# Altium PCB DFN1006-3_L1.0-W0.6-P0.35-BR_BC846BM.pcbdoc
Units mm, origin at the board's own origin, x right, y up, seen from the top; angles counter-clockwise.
Board outline 13.99 x 13.6 mm, 2 copper layers (Top Layer, Bottom Layer), stack 0 mm thick; 1 components, 0 nets, 3 pads, 0 vias.
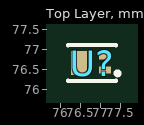
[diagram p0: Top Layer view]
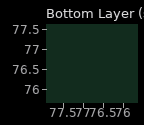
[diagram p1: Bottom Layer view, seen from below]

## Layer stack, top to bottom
Top Layer: signal copper (thickness not stored)
Bottom Layer: signal copper (thickness not stored)

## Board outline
83.835,69.85 69.85,69.85 69.85,83.45 83.835,83.45

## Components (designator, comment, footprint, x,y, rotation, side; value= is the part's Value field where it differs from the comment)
U? "" DFN1006-3_L1.0-W0.6-P0.35-BR_BC846BM 76.8,76.65 r0 top

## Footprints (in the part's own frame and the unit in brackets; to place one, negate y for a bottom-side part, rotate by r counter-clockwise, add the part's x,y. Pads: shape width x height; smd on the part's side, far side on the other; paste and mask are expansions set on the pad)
DFN1006-3_L1.0-W0.6-P0.35-BR_BC846BM [mm]
  rect 0.3x0.17 smd paste+0 mask+0.05: 1(0.325,-0.175) 2(0.325,0.175)
  rect 0.4x0.6 smd paste+0 mask+0.05: 3(-0.325,0)
  silkscreen extent -0.6,-0.45 0.69,0.45

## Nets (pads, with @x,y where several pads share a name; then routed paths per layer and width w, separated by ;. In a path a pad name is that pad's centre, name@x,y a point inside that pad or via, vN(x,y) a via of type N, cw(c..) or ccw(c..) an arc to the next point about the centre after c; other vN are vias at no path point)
pads on no net: U?.1 U?.2 U?.3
